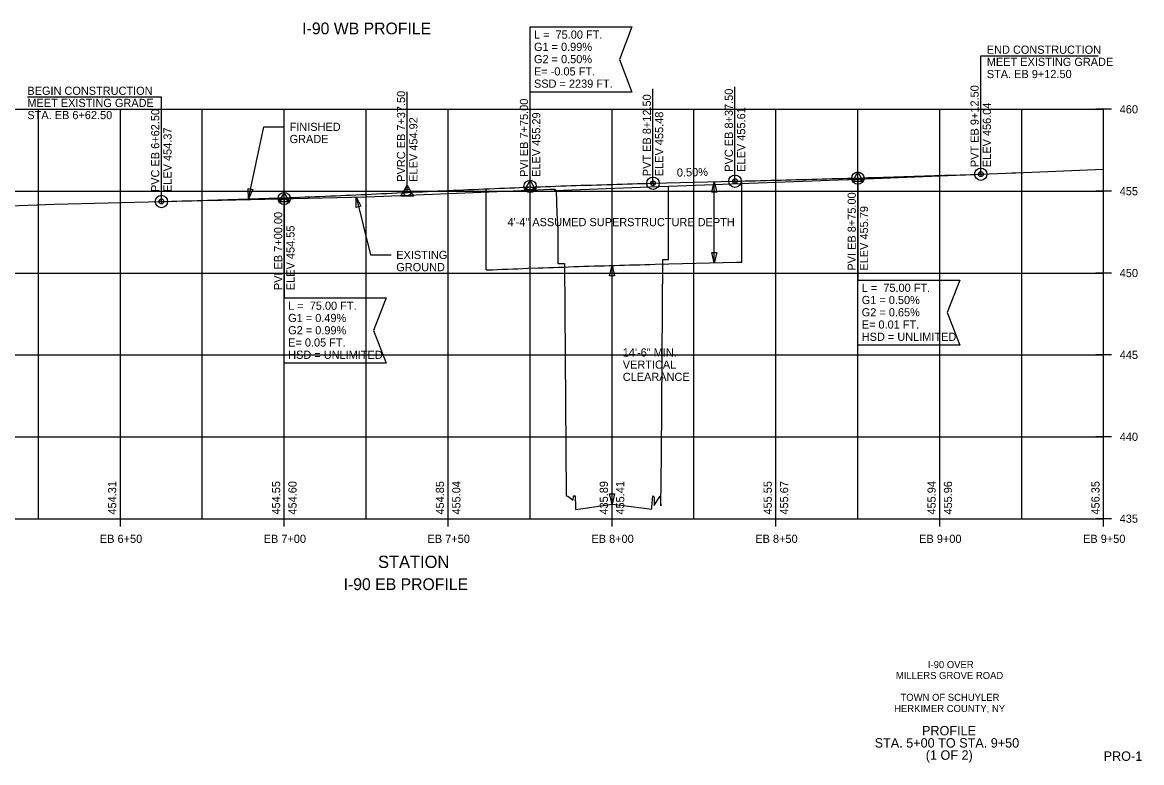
# Model space of a CAD drawing. Extents: x -1473 to -874, y -3319 to -2918.
# Drawn here: x -1215.7 to -874.3, y -3319.4 to -3093.3 of the extents above; entities that cross this region are included whole.
import ezdxf

# ---------------------------------------------------------------- set-up
doc = ezdxf.new("R2010")
doc.units = 0
for name, color, linetype in [('AC_P', 7, 'Continuous'), ('Default', 7, 'Continuous'), ('O_Details_Dimensions_Notes_P', 7, 'Continuous'), ('O_Details_Text Title and Subtitle Proposed_P_T', 7, 'Continuous'), ('XANNOT_P_T', 7, 'Continuous'), ('XAX_P', 7, 'Continuous'), ('XAXTIC_P', 7, 'Continuous'), ('XAXTXT_P_T', 7, 'Continuous'), ('XSAFG1_P_T', 7, 'Continuous'), ('XSAOG1_C', 7, 'Continuous'), ('XSLFG1_P', 7, 'Continuous'), ('XSLOG1', 7, 'Continuous')]:
    doc.layers.add(name, color=color, linetype=linetype)

msp = doc.modelspace()

# ---------------------------------------------------------------- linework, layer by layer
at = {"layer": 'AC_P'}
for p, q in [((-1074.28, -3168.94), (-1074.28, -3144.17)), ((-996.23, -3166.55), (-996.23, -3141.79)), ((-1022.72, -3167.21), (-997.72, -3166.59))]:
    msp.add_line(p, q, dxfattribs=at)
for points in [[(-1074.28, -3168.94), (-1072.31, -3168.86), (-1070.76, -3168.79), (-1069.21, -3168.73), (-1067.66, -3168.67), (-1066.12, -3168.61), (-1064.57, -3168.55), (-1063.02, -3168.49), (-1061.47, -3168.43), (-1058.36, -3168.31), (-1056.82, -3168.26), (-1055.27, -3168.2), (-1053.72, -3168.15), (-1052.17, -3168.09), (-1050.62, -3168.04), (-1049.07, -3167.98), (-1047.52, -3167.93), (-1045.97, -3167.88), (-1044.42, -3167.83), (-1042.87, -3167.78), (-1041.32, -3167.73), (-1039.77, -3167.69), (-1038.22, -3167.64), (-1036.67, -3167.59), (-1035.12, -3167.55), (-1033.57, -3167.5), (-1032.02, -3167.46), (-1030.47, -3167.42), (-1028.92, -3167.37), (-1027.37, -3167.33), (-1025.82, -3167.29), (-1024.27, -3167.25), (-1022.71, -3167.21)], [(-997.72, -3166.59), (-996.23, -3166.55)]]:
    msp.add_lwpolyline(points, dxfattribs=at)
at = {"layer": 'O_Details_Dimensions_Notes_P'}
for p, q in [((-1004.64, -3166.77), (-1004.64, -3142.01)), ((-1035.83, -3240.43), (-1035.83, -3167.57))]:
    msp.add_line(p, q, dxfattribs=at)
for points in [[(-1005.39, -3145.14), (-1004.64, -3142.01), (-1003.89, -3145.14)], [(-1003.89, -3163.65), (-1004.64, -3166.77), (-1005.39, -3163.65)], [(-1036.58, -3170.69), (-1035.83, -3167.57), (-1035.08, -3170.69)], [(-1035.08, -3237.3), (-1035.83, -3240.43), (-1036.58, -3237.3)]]:
    msp.add_lwpolyline(points, close=True, dxfattribs=at)
at = {"layer": 'XANNOT_P_T'}
for p, q in [((-923.34, -3139.7), (-923.34, -3103.58)), ((-923.34, -3103.58), (-887.52, -3103.58)), ((-1023.34, -3142.47), (-1023.34, -3113.67)), ((-998.34, -3141.84), (-998.34, -3113.04)), ((-1173.34, -3116.18), (-1214.22, -3116.18)), ((-1173.34, -3148.04), (-1173.34, -3116.18)), ((-1098.34, -3145.26), (-1098.34, -3114.54)), ((-1060.84, -3143.41), (-1060.84, -3114.61)), ((-1060.84, -3143.41), (-1060.84, -3141.52)), ((-998.33, -3141.84), (-998.33, -3141.1)), ((-960.84, -3140.91), (-962.47, -3141.85)), ((-960.84, -3140.91), (-960.84, -3139.02)), ((-960.84, -3140.91), (-960.84, -3172.01)), ((-960.83, -3140.91), (-959.21, -3141.85)), ((-923.33, -3139.7), (-924.08, -3139.7)), ((-923.33, -3139.7), (-923.33, -3138.95)), ((-923.33, -3139.7), (-923.33, -3140.44)), ((-923.33, -3139.7), (-922.59, -3139.7)), ((-1060.84, -3143.41), (-1062.47, -3144.35)), ((-1060.83, -3143.41), (-1059.21, -3144.35)), ((-1023.33, -3142.47), (-1024.08, -3142.47)), ((-1023.33, -3142.47), (-1023.33, -3141.73)), ((-1023.33, -3142.47), (-1023.33, -3143.21)), ((-1023.33, -3142.47), (-1022.59, -3142.47)), ((-998.33, -3141.84), (-999.08, -3141.84)), ((-998.33, -3141.84), (-998.33, -3142.59)), ((-998.18, -3141.84), (-997.59, -3141.84)), ((-1173.33, -3148.04), (-1174.08, -3148.04)), ((-1173.33, -3148.04), (-1173.33, -3147.29)), ((-1173.33, -3148.04), (-1173.33, -3148.78)), ((-1173.18, -3148.04), (-1172.59, -3148.04)), ((-1135.84, -3147.12), (-1137.47, -3148.06)), ((-1135.84, -3147.12), (-1135.84, -3145.24)), ((-1135.84, -3147.12), (-1135.84, -3177.5)), ((-1135.83, -3147.12), (-1134.21, -3148.06))]:
    msp.add_line(p, q, dxfattribs=at)
for points in [[(-1060.84, -3094.72), (-1029.76, -3094.72), (-1033.58, -3104.66), (-1029.76, -3114.61), (-1060.84, -3114.61)], [(-1060.84, -3141.52), (-1062.47, -3144.35), (-1059.21, -3144.35)], [(-960.84, -3139.02), (-962.47, -3141.85), (-959.21, -3141.85)], [(-1135.84, -3145.24), (-1137.47, -3148.06), (-1134.21, -3148.06)], [(-960.84, -3172.01), (-929.76, -3172.01), (-933.58, -3181.96), (-929.76, -3191.9), (-960.84, -3191.9)], [(-1135.84, -3177.5), (-1104.76, -3177.5), (-1108.58, -3187.44), (-1104.76, -3197.38), (-1135.84, -3197.38)]]:
    msp.add_lwpolyline(points, close=True, dxfattribs=at)
for points in [[(-1100.23, -3146.36), (-1098.34, -3143.09)], [(-1098.34, -3143.09), (-1096.45, -3146.36)], [(-1096.45, -3146.36), (-1100.23, -3146.36)]]:
    msp.add_lwpolyline(points, dxfattribs=at)
for centre, radius in [((-923.33, -3139.7), 1.89), ((-1060.84, -3143.41), 1.88), ((-1023.33, -3142.47), 1.89), ((-998.33, -3141.84), 1.89), ((-998.33, -3141.84), 0.744), ((-960.84, -3140.91), 1.88), ((-923.33, -3139.7), 0.744), ((-923.33, -3139.7), 0.154), ((-1098.33, -3145.26), 1.09), ((-1023.33, -3142.47), 0.744), ((-1023.33, -3142.47), 0.154), ((-998.33, -3141.84), 0.154), ((-1173.33, -3148.04), 1.89), ((-1173.33, -3148.04), 0.744), ((-1173.33, -3148.04), 0.154), ((-1135.84, -3147.12), 1.88)]:
    msp.add_circle(centre, radius, dxfattribs=at)
at = {"layer": 'XAX_P'}
for p, q in [((-1310.84, -3119.88), (-885.84, -3119.88)), ((-1310.84, -3119.88), (-885.84, -3119.88)), ((-1210.84, -3244.88), (-1210.84, -3119.88)), ((-1185.84, -3244.88), (-1185.84, -3119.88)), ((-1160.84, -3244.88), (-1160.84, -3119.88)), ((-1135.84, -3244.88), (-1135.84, -3119.88)), ((-1110.84, -3244.88), (-1110.84, -3119.88)), ((-1085.84, -3244.88), (-1085.84, -3119.88)), ((-1060.84, -3244.88), (-1060.84, -3119.88)), ((-1035.84, -3244.88), (-1035.84, -3119.88)), ((-1010.84, -3244.88), (-1010.84, -3119.88)), ((-985.84, -3244.88), (-985.84, -3119.88)), ((-960.84, -3244.88), (-960.84, -3119.88)), ((-935.84, -3244.88), (-935.84, -3119.88)), ((-910.84, -3244.88), (-910.84, -3119.88)), ((-885.84, -3244.88), (-885.84, -3119.88)), ((-1310.84, -3144.88), (-885.84, -3144.88)), ((-1310.84, -3169.88), (-885.84, -3169.88)), ((-1310.84, -3194.88), (-885.84, -3194.88)), ((-1310.84, -3219.88), (-885.84, -3219.88)), ((-1310.84, -3244.88), (-885.84, -3244.88))]:
    msp.add_line(p, q, dxfattribs=at)
at = {"layer": 'XAXTIC_P'}
for p, q in [((-883.44, -3119.88), (-888.24, -3119.88)), ((-883.44, -3119.88), (-888.24, -3119.88)), ((-883.44, -3144.88), (-888.24, -3144.88)), ((-883.44, -3169.88), (-888.24, -3169.88)), ((-883.44, -3194.88), (-888.24, -3194.88)), ((-883.44, -3219.88), (-888.24, -3219.88)), ((-1210.84, -3244.88), (-1210.84, -3243.68)), ((-1185.84, -3247.28), (-1185.84, -3242.48)), ((-1160.84, -3244.88), (-1160.84, -3243.68)), ((-1135.84, -3247.28), (-1135.84, -3242.48)), ((-1110.84, -3244.88), (-1110.84, -3243.68)), ((-1085.84, -3247.28), (-1085.84, -3242.48)), ((-1060.84, -3244.88), (-1060.84, -3243.68)), ((-1035.84, -3247.28), (-1035.84, -3242.48)), ((-1010.84, -3244.88), (-1010.84, -3243.68)), ((-985.84, -3247.28), (-985.84, -3242.48)), ((-960.84, -3244.88), (-960.84, -3243.68)), ((-935.84, -3247.28), (-935.84, -3242.48)), ((-910.84, -3244.88), (-910.84, -3243.68)), ((-885.84, -3247.28), (-885.84, -3242.48)), ((-883.44, -3244.88), (-888.24, -3244.88))]:
    msp.add_line(p, q, dxfattribs=at)
at = {"layer": 'XSAFG1_P_T'}
for p, q in [((-1146.77, -3147.27), (-1142.12, -3125.21)), ((-1142.12, -3125.21), (-1135.78, -3125.21))]:
    msp.add_line(p, q, dxfattribs=at)
msp.add_lwpolyline([(-1145.39, -3144.37), (-1146.77, -3147.27), (-1146.86, -3144.06)], close=True, dxfattribs=at)
at = {"layer": 'XSAOG1_C'}
for p, q in [((-1113.93, -3146.66), (-1109.58, -3164.33)), ((-1109.58, -3164.33), (-1103.24, -3164.33))]:
    msp.add_line(p, q, dxfattribs=at)
msp.add_lwpolyline([(-1113.91, -3149.87), (-1113.93, -3146.66), (-1112.45, -3149.51)], close=True, dxfattribs=at)
at = {"layer": 'XSLFG1_P'}
msp.add_line((-1023.34, -3142.47), (-998.34, -3141.84), dxfattribs=at)
for points in [[(-998.34, -3141.84), (-996.77, -3141.81), (-995.21, -3141.77), (-993.65, -3141.73), (-992.09, -3141.69), (-990.52, -3141.65), (-988.96, -3141.61), (-987.4, -3141.57), (-985.84, -3141.52), (-984.27, -3141.48), (-982.71, -3141.44), (-981.15, -3141.4), (-979.59, -3141.36), (-978.02, -3141.32), (-976.46, -3141.27), (-974.9, -3141.23), (-973.34, -3141.19), (-971.77, -3141.15), (-970.21, -3141.1), (-968.65, -3141.06), (-967.09, -3141.02), (-965.52, -3140.97), (-963.96, -3140.93), (-962.4, -3140.88), (-959.27, -3140.79), (-957.71, -3140.75), (-956.15, -3140.7), (-954.59, -3140.66), (-953.02, -3140.61), (-951.46, -3140.57), (-949.9, -3140.52), (-948.34, -3140.47), (-946.77, -3140.43), (-945.21, -3140.38), (-943.65, -3140.33), (-942.09, -3140.28), (-940.52, -3140.24), (-938.96, -3140.19), (-937.4, -3140.14), (-935.84, -3140.09), (-934.27, -3140.04), (-932.71, -3139.99), (-931.15, -3139.95), (-929.59, -3139.9), (-928.02, -3139.85), (-926.46, -3139.8), (-924.9, -3139.75), (-923.34, -3139.7)], [(-1098.34, -3145.26), (-1096.77, -3145.19), (-1095.21, -3145.11), (-1093.65, -3145.04), (-1092.09, -3144.96), (-1090.52, -3144.89), (-1088.96, -3144.81), (-1087.4, -3144.74), (-1085.84, -3144.67), (-1084.27, -3144.6), (-1082.71, -3144.53), (-1081.15, -3144.46), (-1079.59, -3144.39), (-1078.02, -3144.33), (-1076.46, -3144.26), (-1074.9, -3144.19), (-1073.34, -3144.13), (-1071.77, -3144.06), (-1070.21, -3144), (-1068.65, -3143.94), (-1067.09, -3143.88), (-1065.52, -3143.82), (-1063.96, -3143.75), (-1062.4, -3143.7), (-1059.27, -3143.58), (-1057.71, -3143.52), (-1056.15, -3143.47), (-1054.59, -3143.41), (-1053.02, -3143.36), (-1051.46, -3143.3), (-1049.9, -3143.25), (-1048.34, -3143.2), (-1046.77, -3143.15), (-1045.21, -3143.09), (-1043.65, -3143.04), (-1042.09, -3143), (-1040.52, -3142.95), (-1038.96, -3142.9), (-1037.4, -3142.85), (-1035.84, -3142.81), (-1034.27, -3142.76), (-1032.71, -3142.72), (-1031.15, -3142.67), (-1029.59, -3142.63), (-1028.02, -3142.59), (-1026.46, -3142.55), (-1024.9, -3142.51), (-1023.34, -3142.47)], [(-1173.34, -3148.04), (-1171.77, -3148), (-1170.21, -3147.96), (-1168.65, -3147.92), (-1167.09, -3147.88), (-1165.52, -3147.83), (-1163.96, -3147.79), (-1162.4, -3147.75), (-1160.84, -3147.7), (-1159.27, -3147.66), (-1157.71, -3147.61), (-1156.15, -3147.57), (-1154.59, -3147.52), (-1153.02, -3147.47), (-1151.46, -3147.42), (-1149.9, -3147.37), (-1148.34, -3147.32), (-1146.77, -3147.27), (-1145.21, -3147.22), (-1143.65, -3147.16), (-1142.09, -3147.11), (-1140.52, -3147.05), (-1138.96, -3147), (-1137.4, -3146.94), (-1134.27, -3146.83), (-1132.71, -3146.77), (-1131.15, -3146.71), (-1129.59, -3146.65), (-1128.02, -3146.59), (-1126.46, -3146.52), (-1124.9, -3146.46), (-1123.34, -3146.4), (-1121.77, -3146.33), (-1120.21, -3146.27), (-1118.65, -3146.2), (-1117.09, -3146.13), (-1115.52, -3146.07), (-1113.96, -3146), (-1112.4, -3145.93), (-1110.84, -3145.86), (-1109.27, -3145.79), (-1107.71, -3145.71), (-1106.15, -3145.64), (-1104.59, -3145.57), (-1103.02, -3145.49), (-1101.46, -3145.42), (-1099.9, -3145.34), (-1098.34, -3145.26)]]:
    msp.add_lwpolyline(points, dxfattribs=at)
at = {"layer": 'XSLOG1'}
for points in [[(-1235.84, -3149.93), (-1205.9, -3148.83), (-1156.87, -3147.63), (-1155.03, -3147.59), (-1110.91, -3146.57), (-1105.47, -3146.44), (-1058.61, -3144.44), (-1054.79, -3144.27), (-1053.64, -3144.25), (-1053.56, -3144.24), (-1053.54, -3144.24), (-1053.31, -3144.31), (-1052.92, -3144.67), (-1052.67, -3151.74), (-1052.33, -3156.5), (-1052.33, -3166.92), (-1051.35, -3166.92), (-1050.34, -3166.92), (-1050.17, -3195.25), (-1049.81, -3237.65), (-1049.77, -3237.96), (-1049.72, -3237.89), (-1049.7, -3237.89), (-1049.28, -3237.98), (-1047.66, -3239.2), (-1047.56, -3238.03), (-1047.55, -3237.89), (-1047.46, -3237.92), (-1047.12, -3237.86), (-1047.03, -3241.26), (-1047.01, -3242.12), (-1044.79, -3241.79), (-1035.83, -3240.43), (-1033.19, -3240.72), (-1023.69, -3241.97), (-1023.66, -3241.23), (-1023.43, -3237.89), (-1023.12, -3238.2), (-1023.02, -3238.21), (-1023.01, -3238.57), (-1022.94, -3240.81), (-1021.5, -3238.4), (-1021.12, -3238.02), (-1021.11, -3238.11), (-1020.92, -3240.99), (-1020.79, -3225.45), (-1020.38, -3165.77), (-1019.64, -3165.77), (-1018.6, -3165.77), (-1018.58, -3144.57), (-1018.58, -3143.36), (-1018.58, -3143.36), (-1018.58, -3143.35), (-1018.54, -3143.35), (-963.99, -3141.32), (-963.54, -3141.3), (-915.66, -3139.39), (-913.81, -3139.32), (-912.59, -3139.26), (-885.84, -3138.13)], [(-1053.56, -3144.24), (-1053.33, -3144.65), (-1053.31, -3144.68), (-1027.13, -3143.69), (-1018.58, -3143.36)]]:
    msp.add_lwpolyline(points, dxfattribs=at)

# ---------------------------------------------------------------- texts
at = {"layer": 'Default'}
for s, height, p in [('I-90 OVER', 2.16, (-939.47, -3290.5)), ('MILLERS GROVE ROAD', 2.16, (-949.22, -3293.84)), ('TOWN OF SCHUYLER', 2.16, (-947.83, -3300.51)), ('HERKIMER COUNTY, NY', 2.16, (-949.77, -3303.92)), ('PROFILE ', 2.88, (-941.26, -3311.05)), ('STA. 5+00 TO STA. 9+50', 2.88, (-955.71, -3314.78)), ('(1 OF 2)', 2.88, (-940.12, -3318.5)), ('PRO-1', 2.88, (-885.84, -3318.82))]:
    msp.add_text(s, height=height, dxfattribs=at).set_placement(p)
at = {"layer": 'O_Details_Dimensions_Notes_P'}
for s, p in [('4\'-4" ASSUMED SUPERSTRUCTURE DEPTH', (-1067.73, -3155.57)), ('14\'-6" MIN.', (-1032.56, -3195.38)), ('VERTICAL', (-1032.56, -3199.09)), ('CLEARANCE', (-1032.56, -3202.81))]:
    msp.add_text(s, height=2.496, dxfattribs=at).set_placement(p)
at = {"layer": 'O_Details_Text Title and Subtitle Proposed_P_T'}
for s, p in [('I-90 WB PROFILE', (-1130.36, -3097)), ('I-90 EB PROFILE', (-1117.74, -3266.68))]:
    msp.add_text(s, height=3.6, dxfattribs=at).set_placement(p)
at = {"layer": 'XANNOT_P_T'}
for s, p in [('L =  75.00 FT.', (-1059.65, -3098.32)), ('G1 = 0.99%', (-1059.65, -3102.07)), ('END CONSTRUCTION', (-921.49, -3102.93)), ('G2 = 0.50%', (-1059.65, -3105.81)), ('E= -0.05 FT.', (-1059.65, -3109.56)), ('MEET EXISTING GRADE', (-921.49, -3106.64)), ('SSD = 2239 FT.', (-1059.65, -3113.3)), ('STA. EB 9+12.50', (-921.49, -3110.36)), ('BEGIN CONSTRUCTION', (-1214.22, -3115.47)), ('MEET EXISTING GRADE', (-1214.22, -3119.18)), ('STA. EB 6+62.50', (-1214.22, -3122.89)), ('L =  75.00 FT.', (-959.65, -3175.62)), ('L =  75.00 FT.', (-1134.65, -3181.1)), ('G1 = 0.50%', (-959.65, -3179.36)), ('G1 = 0.49%', (-1134.65, -3184.85)), ('G2 = 0.65%', (-959.65, -3183.11)), ('E= 0.01 FT.', (-959.65, -3186.85)), ('G2 = 0.99%', (-1134.65, -3188.59)), ('HSD = UNLIMITED', (-959.65, -3190.59)), ('E= 0.05 FT.', (-1134.65, -3192.33)), ('HSD = UNLIMITED', (-1134.65, -3196.08))]:
    msp.add_text(s, height=2.496, dxfattribs=at).set_placement(p)
for s, height, rotation, p in [('PVC EB 8+37.50', 2.5008, 90, (-998.96, -3138.96)), ('PVT EB 9+12.50', 2.5008, 90, (-923.96, -3137.54)), ('PVRC EB 7+37.50', 2.5008, 90, (-1098.96, -3142.02)), ('PVI EB 7+75.00', 2.5008, 90, (-1061.46, -3140.53)), ('PVT EB 8+12.50', 2.5008, 90, (-1023.96, -3140.31)), ('PVC EB 6+62.50', 2.5008, 90, (-1173.96, -3145.16)), ('ELEV 455.29', 2.5008, 90, (-1057.71, -3140.53)), ('ELEV 455.48 ', 2.5008, 90, (-1020.21, -3140.31)), ('ELEV 455.61 ', 2.5008, 90, (-995.21, -3138.96)), ('ELEV 456.04 ', 2.5008, 90, (-920.21, -3137.54)), ('ELEV 454.92 ', 2.5008, 90, (-1095.21, -3142.02)), ('ELEV 454.37 ', 2.5008, 90, (-1170.21, -3145.16)), ('0.50% ', 2.501, 1.4321, (-1016.03, -3140.46)), ('PVI EB 8+75.00', 2.5008, 90, (-961.46, -3169.14)), ('PVI EB 7+00.00', 2.5008, 90, (-1136.46, -3175.1)), ('ELEV 455.79', 2.5008, 90, (-957.71, -3169.14)), ('ELEV 454.55', 2.5008, 90, (-1132.71, -3175.1)), ('454.31', 2.501, 90, (-1187.09, -3243.63)), ('454.55', 2.501, 90, (-1137.09, -3243.63)), ('454.60', 2.501, 90, (-1132.09, -3243.63)), ('454.85', 2.501, 90, (-1087.09, -3243.63)), ('455.04', 2.501, 90, (-1082.09, -3243.63)), ('435.89', 2.501, 90, (-1037.09, -3243.63)), ('455.41', 2.501, 90, (-1032.09, -3243.63)), ('455.55', 2.501, 90, (-987.09, -3243.63)), ('455.67', 2.501, 90, (-982.09, -3243.63)), ('455.94', 2.501, 90, (-937.09, -3243.63)), ('455.96', 2.501, 90, (-932.09, -3243.63)), ('456.35', 2.501, 90, (-887.09, -3243.63))]:
    msp.add_text(s, height=height, rotation=rotation, dxfattribs=at).set_placement(p)
at = {"layer": 'XAXTXT_P_T'}
for s, height, p in [('460', 2.501, (-880.94, -3121.13)), ('460', 2.501, (-880.94, -3121.13)), ('455', 2.501, (-880.94, -3146.13)), ('450', 2.501, (-880.94, -3171.13)), ('445', 2.501, (-880.94, -3196.13)), ('440', 2.501, (-880.94, -3221.13)), ('435', 2.501, (-880.94, -3246.13)), ('EB 6+50', 2.501, (-1192.1, -3252.28)), ('EB 7+00', 2.501, (-1142.13, -3252.28)), ('EB 7+50', 2.501, (-1092.13, -3252.28)), ('EB 8+00', 2.501, (-1042.13, -3252.28)), ('EB 8+50', 2.501, (-992.13, -3252.28)), ('EB 9+00', 2.501, (-942.13, -3252.28)), ('EB 9+50', 2.501, (-892.13, -3252.28)), ('STATION', 3.754, (-1107.23, -3259.94))]:
    msp.add_text(s, height=height, dxfattribs=at).set_placement(p)
at = {"layer": 'XSAFG1_P_T'}
for s, p in [('FINISHED ', (-1134.21, -3126.49)), ('GRADE', (-1134.21, -3130.2))]:
    msp.add_text(s, height=2.496, dxfattribs=at).set_placement(p)
at = {"layer": 'XSAOG1_C'}
for s, p in [('EXISTING ', (-1101.67, -3165.6)), ('GROUND', (-1101.67, -3169.32))]:
    msp.add_text(s, height=2.496, dxfattribs=at).set_placement(p)

doc.saveas('drawing.dxf')
